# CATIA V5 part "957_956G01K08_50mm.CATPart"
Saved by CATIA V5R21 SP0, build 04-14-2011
Part number: 957_956G01K08_50mm
Bounding box of the stored display mesh (mm): x -33.75 to 33.05, y -126.3 to -25.1, z -8 to 12
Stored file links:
  C:\Users\ALI OZGUN\Desktop\alhan\957_956G01K08_50mm.CATPart
  C:\Users\ALI OZGUN\Desktop\alhan\960B01P01.CATPart
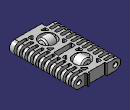
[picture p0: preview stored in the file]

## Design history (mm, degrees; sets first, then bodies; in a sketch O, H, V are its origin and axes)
Set1
  Plane1: type Normal, Curve Sketch12, RefPoint Sketch12.P3
  Point1: type Center, Curve edge [face of Pad1 from Sketch1.L2 | face of Pocket3 from Sketch4.A1]
  Line1: type PtDir, RefPoint Point1, Direction face of Pad1 from Sketch1.L2, Start 0, End 20
Set2
  Plane2: stored without definition
  Point2: stored without definition
  Line2: stored without definition
  Line3: type PtDir, RefPoint {point type Center, Curve edge [face of Pocket7 from Sketch9.L1 | face of Pocket4 from Sketch6.A2]}, Direction face of Pocket7 from Sketch9.L1, Start 0, End 20
Body1 (main body)
  Sketch1 on zx-plane, origin (0, 0, 0), H (-1, 0, 0), V (0, 0, 1)
    construction line L1 (-25.05, 0) -> (25.75, 0)
    point P1 (-25.05, 0)
    line L2 (-25.05, 8) -> (25.75, 8)
    line L3 (25.75, -8) -> (-25.05, -8)
    arc A1 centre (25.75, 0) radius 8 from (25.75, 8) to (25.75, -8) cw
    arc A2 centre (-25.05, 0) radius 8 from (-25.05, -8) to (-25.05, 8) cw
    distance L1 L2 = 8
    distance P1 V = 25.05
    length L1 = 50.8
    coincidence: P1 H
    horizontal: L1 H
    tangency: A1 L2, A2 L2, A1 L3, A2 L3
  Pad1: profile Sketch1, direction (0, 1, 0), length 127.5, mirrored extent
  Sketch2 on face of Pad1 from Sketch1.L2, origin (0, 0, 8), H (1, 0, 0), V (0, 1, 0)
    line L1 (-50.9731, -119.3) -> (-16.75, -119.3)
    line L2 (-15.75, -120.3) -> (-15.75, -122.5)
    line L3 (-16.75, -123.5) -> (-50.9731, -123.5)
    line L4 (-50.9731, -123.5) -> (-50.9731, -119.3)
    arc A1 centre (-16.75, -120.3) radius 1 from (-16.75, -119.3) to (-15.75, -120.3) cw
    arc A2 centre (-16.75, -122.5) radius 1 from (-15.75, -122.5) to (-16.75, -123.5) cw
    reference projected line E1 (-25.75, -127.5) -> (25.05, -127.5) from edge [start face of Pad1 | face of Pad1 from Sketch1.L2]
    reference projected line E2 through (-25.75, 0) direction (0, 1) from axis of face of Pad1 from Sketch1.A1
    radius A1 = 1
    radius A2 = 1 {= Sketch2.radius(A1)}
    length L4 = 4.2
    distance L3 E1 = 4
    distance L2 E2 = 10
    horizontal: L1 H, L3 H
    vertical: L2 V, L4 V
    tangency: A1 L1, A1 L2, A2 L2, A2 L3
  Pocket1: profile Sketch2, direction (0, 0, -1), length 30, mirrored extent
  RectPattern1: of Pocket1, direction 1 instances 32, spacing 8.2, along axis of face of Pad1 from Sketch1.A1
  Sketch3 on face of Pad1 from Sketch1.L2, origin (0, 0, 8), H (1, 0, 0), V (0, 1, 0)
    line L1 (50.2731, -123.4) -> (50.2731, -127.6)
    line L2 (50.2731, -127.6) -> (16.05, -127.6)
    arc A1 centre (16.0504, -126.5996) radius 1.0004 from (16.05, -127.6) to (15.05, -126.6) cw
    line L3 (15.05, -126.6) -> (15.05, -124.4)
    arc A2 centre (16.0504, -124.4004) radius 1.0004 from (15.05, -124.4) to (16.05, -123.4) cw
    line L4 (16.05, -123.4) -> (50.2731, -123.4)
    reference projected line E2 through (25.05, 0) direction (0, 1) from axis of face of Pad1 from Sketch1.A2
    reference projected line E3 (-25.75, -127.5) -> (25.05, -127.5) from edge [start face of Pad1 | face of Pad1 from Sketch1.L2]
    distance L3 E2 = 10
    distance L4 E3 = 4.1
  Pocket2: profile Sketch3, direction (0, 0, -1), length 30
  RectPattern2: of Pocket2, direction 1 instances 32, spacing 8.2, along axis of face of Pad1 from Sketch1.A2
  RemoveFace1: RemoveFaces (face of RectPattern2; face of RectPattern2)
  RemoveFace2: RemoveFaces (face of RectPattern1; face of RectPattern1; face of Pad1 from Sketch1.A1)
  Sketch4 on face of Pad1 from Sketch1.L2, origin (0, 0, 8), H (1, 0, 0), V (0, 1, 0)
    circle A1 centre (0, -101.5) radius 12
    point P1 (0, -101.5)
    point P2 (-13, -84.5)
    line L1 (-12, -84.5) -> (-7.7574, -84.5)
    line L2 (13, -85.5) -> (13, -89.7426)
    line L3 (-7.7574, -118.5) -> (-12, -118.5)
    line L4 (-13, -117.5) -> (-13, -113.2574)
    point P3 (13, -84.5)
    point P4 (13, -118.5)
    point P5 (-13, -118.5)
    reference projected line E1 (-25.75, -127.5) -> (25.05, -127.5) from edge [start face of Pad1 | face of Pad1 from Sketch1.L2]
    line L5 (7.0503, -86.2071) -> (11.2929, -90.4497)
    line L6 (-7.0503, -86.2071) -> (-11.2929, -90.4497)
    line L7 (-11.2929, -112.5503) -> (-7.0503, -116.7929)
    line L8 (7.0503, -116.7929) -> (11.2929, -112.5503)
    arc A2 centre (12, -117.5) radius 1 from (12, -118.5) to (13, -117.5) ccw
    point P6 (12, -118.5)
    arc A3 centre (-12, -117.5) radius 1 from (-12, -118.5) to (-13, -117.5) cw
    arc A4 centre (-12, -85.5) radius 1 from (-12, -84.5) to (-13, -85.5) ccw
    arc A5 centre (12, -85.5) radius 1 from (12, -84.5) to (13, -85.5) cw
    line L9 (13, -113.2574) -> (13, -117.5)
    line L10 (7.7574, -84.5) -> (12, -84.5)
    line L11 (-13, -89.7426) -> (-13, -85.5)
    line L12 (12, -118.5) -> (7.7574, -118.5)
    arc A6 centre (12, -113.2574) radius 1 from (13, -113.2574) to (11.2929, -112.5503) ccw
    arc A7 centre (7.7574, -85.5) radius 1 from (7.7574, -84.5) to (7.0503, -86.2071) ccw
    arc A8 centre (12, -89.7426) radius 1 from (11.2929, -90.4497) to (13, -89.7426) ccw
    arc A9 centre (-7.7574, -85.5) radius 1 from (-7.7574, -84.5) to (-7.0503, -86.2071) cw
    arc A10 centre (-12, -89.7426) radius 1 from (-13, -89.7426) to (-11.2929, -90.4497) ccw
    arc A11 centre (-12, -113.2574) radius 1 from (-13, -113.2574) to (-11.2929, -112.5503) cw
    arc A12 centre (-7.7574, -117.5) radius 1 from (-7.0503, -116.7929) to (-7.7574, -118.5) cw
    arc A13 centre (7.7574, -117.5) radius 1 from (7.7574, -118.5) to (7.0503, -116.7929) cw
    point P42 (-13, -72.3)
    line L13 (-12, -72.3) -> (12, -72.3)
    line L14 (13, -73.3) -> (13, -78.3)
    line L15 (12, -79.3) -> (-12, -79.3)
    line L16 (-13, -78.3) -> (-13, -73.3)
    point P43 (13, -79.3)
    point P44 (-13, -79.3)
    arc A14 centre (-12, -73.3) radius 1 from (-12, -72.3) to (-13, -73.3) ccw
    point P45 (-12, -72.3)
    point P46 (-13, -73.3)
    arc A15 centre (12, -73.3) radius 1 from (12, -72.3) to (13, -73.3) cw
    point P48 (12, -72.3)
    point P49 (13, -73.3)
    arc A16 centre (12, -78.3) radius 1 from (13, -78.3) to (12, -79.3) cw
    point P51 (13, -78.3)
    point P52 (12, -79.3)
    arc A17 centre (-12, -78.3) radius 1 from (-12, -79.3) to (-13, -78.3) cw
    point P54 (-12, -79.3)
    point P55 (-13, -78.3)
    axis line L17 (15.2688, -101.5) -> (-36.2816, -101.5)
    point P59 (-13, -130.7)
    point P60 (13, -123.7)
    point P61 (-13, -123.7)
    point P62 (-12, -130.7)
    point P63 (-13, -129.7)
    point P65 (12, -130.7)
    point P66 (13, -129.7)
    point P68 (13, -124.7)
    point P69 (12, -123.7)
    point P71 (-12, -123.7)
    point P72 (-13, -124.7)
    line L18 (-12, -130.7) -> (12, -130.7)
    line L19 (13, -129.7) -> (13, -124.7)
    line L20 (12, -123.7) -> (-12, -123.7)
    line L21 (-13, -124.7) -> (-13, -129.7)
    arc A18 centre (-12, -129.7) radius 1 from (-12, -130.7) to (-13, -129.7) cw
    arc A19 centre (12, -129.7) radius 1 from (12, -130.7) to (13, -129.7) ccw
    arc A20 centre (12, -124.7) radius 1 from (13, -124.7) to (12, -123.7) ccw
    arc A21 centre (-12, -124.7) radius 1 from (-12, -123.7) to (-13, -124.7) ccw
    radius A1 = 12
    distance L1 L3 = 34
    distance L4 V = 13
    distance P1 L1 = 17
    distance L3 E1 = 9
    angle L5 L1 = 45
    angle L6 L1 = 45
    angle L7 L3 = 45
    angle L8 L3 = 135
    radius A2 = 1
    radius A3 = 1 {= Sketch4.radius(A2)}
    distance P2 P3 = 26
    radius A4 = 1 {= Sketch4.radius(A2)}
    radius A5 = 1 {= Sketch4.radius(A2)}
    distance L8 A2 = 5
    distance L7 A3 = 5
    distance L6 A4 = 5
    distance L5 A5 = 5
    radius A6 = 1
    radius A7 = 1 {= Sketch4.radius(A6)}
    radius A8 = 1 {= Sketch4.radius(A6)}
    radius A9 = 1 {= Sketch4.radius(A6)}
    radius A10 = 1 {= Sketch4.radius(A6)}
    radius A11 = 1 {= Sketch4.radius(A6)}
    radius A12 = 1 {= Sketch4.radius(A6)}
    radius A13 = 1 {= Sketch4.radius(A6)}
    distance L1 L15 = 5.2
    distance P44 P42 = 7
    radius A14 = 1
    radius A15 = 1 {= Sketch4.radius(A14)}
    radius A16 = 1 {= Sketch4.radius(A14)}
    radius A17 = 1 {= Sketch4.radius(A14)}
    coincidence: P1 V, L3 P4, L2 P4, L3 P5, L4 P5, L1 P2, L4 P2, L1 P3, L2 P3, L2 L9, L1 L10, L4 L11, P6 L3, P42 L4, P43 L2, L13 P42, L16 P42, L14 P43, L15 P43, L15 P44, L16 P44, L17 P1
    horizontal: L1 H, L3 H, L10 H, L13 H, L15 H, L17 H
    vertical: L2 V, L4 V, L9 V, L11 V, L14 V, L16 V
    tangency: A2 L3, A2 L2, A3 L3, A3 L4, A4 L1, A4 L4, A5 L1, A5 L2, L12 A2, A6 L9, A6 L8, A7 L10, A7 L5, A8 L5, A8 L2, A9 L1, A9 L6, A10 L11, A10 L6, A11 L4, A11 L7, A12 L7, A12 L3, A13 L12, A13 L8, A14 L13, A14 L16, A15 L13, A15 L14, A16 L14, A16 L15, A17 L15, A17 L16
    symmetry: P42 P59 L17, P43 P60 L17, P44 P61 L17, P45 P62 L17, P46 P63 L17, P48 P65 L17, P49 P66 L17, P51 P68 L17, P52 P69 L17, P54 P71 L17, P55 P72 L17, L13 L18 L17, L14 L19 L17, L15 L20 L17, L16 L21 L17, A14 A18 L17, A15 A19 L17, A16 A20 L17, A17 A21 L17
  Pocket3: profile Sketch4, direction (0, 0, -1), length 30
  RectPattern3: of Pocket3, direction 1 instances 5, spacing 51.4, along axis of face of Pad1 from Sketch1.A1
  RemoveFace3: RemoveFaces (face of Pocket3 from Sketch4.L19; face of Pocket3 from Sketch4.A20; face of Pocket3 from Sketch4.L20; face of Pocket3 from Sketch4.L21; face of Pocket3 from Sketch4.A21; face of Pocket2 from Sketch3.A1; face of Pocket2 from Sketch3.L3; face of Pocket2 from Sketch3.A2; face of Pocket2 from Sketch3.L4)
  Sketch5 on start face of Pad1, origin (0, -127.5, 0), H (1, 0, 0), V (0, 0, 1)
    projected line E3 (-15.75, 8) -> (-15.75, -8) from face of Pocket1 from Sketch2.L2
    projected line E4 (-15.75, 8) -> (-15.75, -8) from face of Pocket1 from Sketch2.L2
  Pad2: profile Sketch5, direction (0, -1, 0), length 12
  Sketch6 on zx-plane, origin (0, 0, 0), H (-1, 0, 0), V (0, 0, 1)
    circle A1 centre (25.75, 0) radius 3.5
    point P1 (25.75, 0)
    circle A2 centre (-25.05, 0) radius 3.5
    reference projected arc E1 centre (25.75, 0) radius 8 from (25.75, -8) to (25.75, 8) ccw from edge [face of RectPattern1 | face of Pad1 from Sketch1.A1]
    reference projected arc E2 centre (-25.05, 0) radius 8 from (-25.05, 8) to (-25.05, -8) ccw from edge [face of Pad1 from Sketch1.A2 | end face of Pad1]
    radius A2 = 3.5
    radius A1 = 3.5
    coincidence: P1 H
    concentricity: A1 E1, A2 E2
  Pocket4: profile Sketch6, direction (0, -1, 0), length 184, mirrored extent
  Sketch7 on face of Pad2 from Sketch5.E4, origin (-15.75, 0, 0), H (0, -1, 0), V (0, 0, 1)
    line L1 (131.394, 4.4412) -> (136.4149, 4.4412)
    line L2 (136.4149, 4.4412) -> (136.4149, -5.0929)
    line L3 (136.4149, -5.0929) -> (131.394, -5.0929)
    line L4 (131.394, -5.0929) -> (131.394, 4.4412)
    horizontal: L1 H, L3 H
    vertical: L2 V, L4 V
  Pocket5: profile Sketch7, direction (1, 0, 0), length 21
  Sketch8 on face of Pad2, origin (0, 0, -8), H (1, 0, 0), V (0, -1, 0)
    line L1 (0.8391, 137.9218) -> (7.819, 137.9218)
    line L2 (7.819, 137.9218) -> (7.819, 135.2061)
    line L3 (7.819, 135.2061) -> (0.8391, 135.2061)
    line L4 (0.8391, 135.2061) -> (0.8391, 137.9218)
    horizontal: L1 H, L3 H
    vertical: L2 V, L4 V
  Pocket6: profile Sketch8, direction (0, 0, 1), length 7
  Sketch9 on face of Pad2, origin (0, 0, -8), H (1, 0, 0), V (0, -1, 0)
    line L1 (-41.5561, 126.3) -> (43.6093, 126.3)
    line L2 (43.6093, 126.3) -> (43.6093, 25.1)
    line L3 (43.6093, 25.1) -> (-41.5561, 25.1)
    line L4 (-41.5561, 25.1) -> (-41.5561, 126.3)
    reference projected line E1 (-16.75, 25.1) -> (-25.75, 25.1) from edge [face of Pad1 from Sketch1.L3 | face of RectPattern1]
    length L2 = 101.2
    horizontal: L1 H, L3 H
    vertical: L2 V, L4 V
    coincidence: L3 E1
  Pocket7: profile Sketch9, direction (0, 0, 1), length 34, mirrored extent, outer side
  RemoveFace4: RemoveFaces (face of RectPattern2; face of RectPattern2; face of RectPattern2; face of RectPattern2; face of RectPattern2), deactivated
  RemoveFace5: RemoveFaces (face of Pocket1 from Sketch2.L3; face of Pad1 from Sketch1.A1; face of Pocket4 from Sketch6.A1; face of Pocket1 from Sketch2.A2)
  Sketch10 on face of Pocket1 from Sketch2.L2, origin (-15.75, 0, 0), H (0, -1, 0), V (0, 0, 1)
    line L1 (121.635, 5.0181) -> (124.8716, 5.0181)
    line L2 (124.8716, 5.0181) -> (124.8716, -4.4654)
    line L3 (124.8716, -4.4654) -> (121.635, -4.4654)
    line L4 (121.635, -4.4654) -> (121.635, 5.0181)
    horizontal: L1 H, L3 H
    vertical: L2 V, L4 V
  Pocket8: profile Sketch10, direction (1, 0, 0), length 26
  Sketch11 on face of Pad2, origin (0, 0, -8), H (1, 0, 0), V (0, -1, 0)
    point P1 (0, 124.8571)
    line L1 (0, 124.8571) -> (9.0453, 124.8571)
    line L2 (9.0453, 124.8571) -> (9.0453, 122.1462)
    line L3 (9.0453, 122.1462) -> (0, 122.1462)
    line L4 (0, 122.1462) -> (0, 124.8571)
    coincidence: P1 V
    horizontal: L1 H, L3 H
    vertical: L2 V, L4 V
  Pocket9: profile Sketch11, direction (0, 0, 1), length 10
Body2
  Solid1: linked copy from another document
  Translate1: Direction yz-plane, Length 50.8, ToTransfor Solid1
Body3
  Sketch12 on xy-plane, origin (0, 0, 0), H (1, 0, 0), V (0, 1, 0)
    point P1 (0, -101.5)
    reference projected circle E1 centre (0, -101.5) radius 12 from edge [face of Pad1 from Sketch1.L2 | face of Pocket3 from Sketch4.A1]
    line L1 (-12.5, -101.5) -> (12.5, -101.5)
    point P3 (12.5, -101.5)
    length L1 = 25
    distance P3 V = 12.5
    concentricity: P1 E1
    horizontal: L1 H
    coincidence: L1 P1
  Sketch13 on Plane1, origin (12.5, 0, 0), H (0, 1, 0), V (0, 0, 1)
    circle A1 centre (-101.5, 0) radius 1.5
    point P1 (-101.5, 0)
    reference projected point E1 (-101.5, 0) from Sketch12.P3
    radius A1 = 1.5
    coincidence: P1 E1
  Slot1: profile Sketch13, centre curve Sketch12
  Translate2: Direction xy-plane, Length 4, ToTransfor Slot1
  Rotate1: ToTransfor Translate2, Axis Line1, Angle 0
  RectPattern4: of the body so far, direction 1 instances 5, spacing 51.4, along axis of face of Pad1 from Sketch1.A2, deactivated
Body4
  Sketch14 on yz-plane, origin (0, 0, 0), H (0, 1, 0), V (0, 0, 1)
    circle A1 centre (-101.5, 4) radius 8
    circle A2 centre (-101.5, 3.7143) radius 1.75
    radius A1 = 8
    radius A2 = 1.75
  Pad3: profile Sketch14, direction (1, 0, 0), length 8, mirrored extent
  Fillet1: radius 2, on edge [face of Pad3 from Sketch14.A1 | end face of Pad3]; edge [start face of Pad3 | face of Pad3 from Sketch14.A1]
  Rotate2: ToTransfor Fillet1, Axis Line1, Angle 0
  RectPattern5: of the body so far, direction 1 instances 5, spacing 51.4, along axis of face of Pad1 from Sketch1.A2, deactivated
Body5
  Solid2: solid without history
  Pocket10: profile Sketch16, direction (0, 0, 1), length 27, opposite side length 43
  Sketch15 on xy-plane, origin (0, 0, 0), H (1, 0, 0), V (0, 1, 0)
Body6
  Solid3: solid without history
  Sketch16 on xy-plane, origin (0, 0, 0), H (1, 0, 0), V (0, 1, 0)
    line L1 (61.141, -26.3381) -> (-51.0359, -26.3381)
    line L2 (-51.0359, -26.3381) -> (-51.0359, 120.7423)
    line L3 (-51.0359, 120.7423) -> (61.141, 120.7423)
    line L4 (61.141, 120.7423) -> (61.141, -26.3381)
    line L5 (-54.2992, -79.4817) -> (38.9401, -79.4817)
    line L6 (38.9401, -79.4817) -> (38.9401, -125.5216)
    line L7 (38.9401, -125.5216) -> (-54.2992, -125.5216)
    line L8 (-54.2992, -125.5216) -> (-54.2992, -79.4817)
    horizontal: L1 H, L3 H, L5 H, L7 H
    vertical: L2 V, L4 V, L6 V, L8 V
  Pad4: profile Sketch16, direction (0, 0, 1), length 27, opposite side length 59
Body7
  Solid4: linked copy from another document
  Translate3: Direction yz-plane, ToTransfor Solid4, Length 50.8
  Rotate3: ToTransfor Translate3, Angle 38, Axis Line3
